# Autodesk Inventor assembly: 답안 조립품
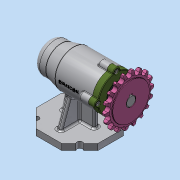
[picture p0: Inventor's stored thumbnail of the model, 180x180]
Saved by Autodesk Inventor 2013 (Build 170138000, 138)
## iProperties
Created: 2021-01
Part Number: 답안 조립품
Document SubType Name: Assembly
Designer: Administrator
Author: Administrator
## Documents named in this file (12)
- C:\Users\Administrator\Desktop\710106V1029\답안 조립품.iam
- C:\Users\Administrator\Desktop\710106V1029\본체.ipt
- C:\Users\Administrator\Desktop\710106V1029\베어링 51202.ipt
- C:\Users\Administrator\Desktop\710106V1029\볼트 M4.ipt
- C:\Users\Administrator\Desktop\710106V1029\어댑터슬리브.ipt
- C:\Users\Administrator\Desktop\710106V1029\커버.ipt
- C:\Users\Administrator\Desktop\710106V1029\베어링 6004.ipt
- C:\Users\Administrator\Desktop\710106V1029\오일 실.ipt
- C:\Users\Administrator\Desktop\710106V1029\멈춤나사 M3.ipt
- C:\Users\Administrator\Desktop\710106V1029\스프로킷.ipt
- C:\Users\Administrator\Desktop\710106V1029\축.ipt
- C:\Users\Administrator\Desktop\710106V1029\키 5 x 5 x 14.ipt
